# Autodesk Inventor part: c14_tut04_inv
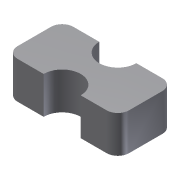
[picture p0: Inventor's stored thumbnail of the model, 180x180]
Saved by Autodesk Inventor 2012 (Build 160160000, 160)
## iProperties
Created: 2010-04
Part Number: c14_tut04_inv
Document SubType Name: Modeling
Designer: CADSoft
Density: 1 g/cm^3
Material: Default
Author: CADSoft
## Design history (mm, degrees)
sketch "Sketch1"
  geometry: L1 (33.666, 15.267)-(33.666, -14.733); L2 (-26.334, -14.733)-(-26.334, 15.267); L3 (-26.334, 15.267)-(-6.334, 15.267); L4 (13.666, 15.267)-(33.666, 15.267); L5 (33.666, -14.733)-(13.666, -14.733); L6 (-6.334, -14.733)-(-26.334, -14.733); A1 r 10 centre (3.666, 15.267) between (-6.334, 15.267) and (13.666, 15.267); A2 r 10 centre (3.666, -14.733) between (13.666, -14.733) and (-6.334, -14.733); 1 further point
  constraints: 12 end point, 5 parallel, 4 equal length, 4 point on circle, 2 centre point, 2 horizontal, 2 horizontal alignment, 2 perpendicular, 1 equal radius
  dimensions: "d0" = 60 distance between parallel lines of L1 L2 (= LEN); "d1" = 30 distance of L2.start L2.end (= WID); "d2" = 10 radius of A1 (= RAD)
extrude "Extrusion1" new body sketch "Sketch1" distance "d3" = 20 (= EXT); taper "d4" = 0 deg
fillet "Fillet1" dims "d5" = 6 (= FILLET)
body "Solid1"
other parameters: "LEN" = 60 [user parameter; used in 5 equation terms], "WID" = 30 (= 0.5 x LEN) [user parameter; used in 1 equation term], "RAD" = 10 (= 0.166667 x LEN) [user parameter; used in 1 equation term], "EXT" = 20 (= 0.333333 x LEN) [user parameter; used in 1 equation term], "FILLET" = 6 (= 0.1 x LEN) [user parameter; used in 1 equation term]
